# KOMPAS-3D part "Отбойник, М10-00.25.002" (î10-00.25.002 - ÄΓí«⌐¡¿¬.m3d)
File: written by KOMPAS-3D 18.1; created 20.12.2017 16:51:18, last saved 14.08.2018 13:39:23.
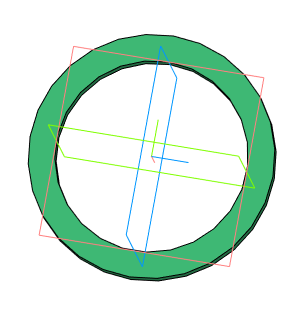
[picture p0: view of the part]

Document properties: Автор: Мирончук; Организация: Мирончук; Полное имя файла: D:\Magna\Магна Ins\Магна ins 10\М10-00.00.000\3Д\М10-00.25.002 - Отбойник.m3d

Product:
- Part/product: Отбойник  | designation М10-00.25.002
    Масса: 0.00747423
    Раздел спецификации: Детали
    Форматы листов документа: A4
    source file: М10-00.25.002 - Отбойник.cdw

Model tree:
1. Эскиз:1
2. Операция вращения:1
     Угол 1 = 360

Expressions: 63.8/2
